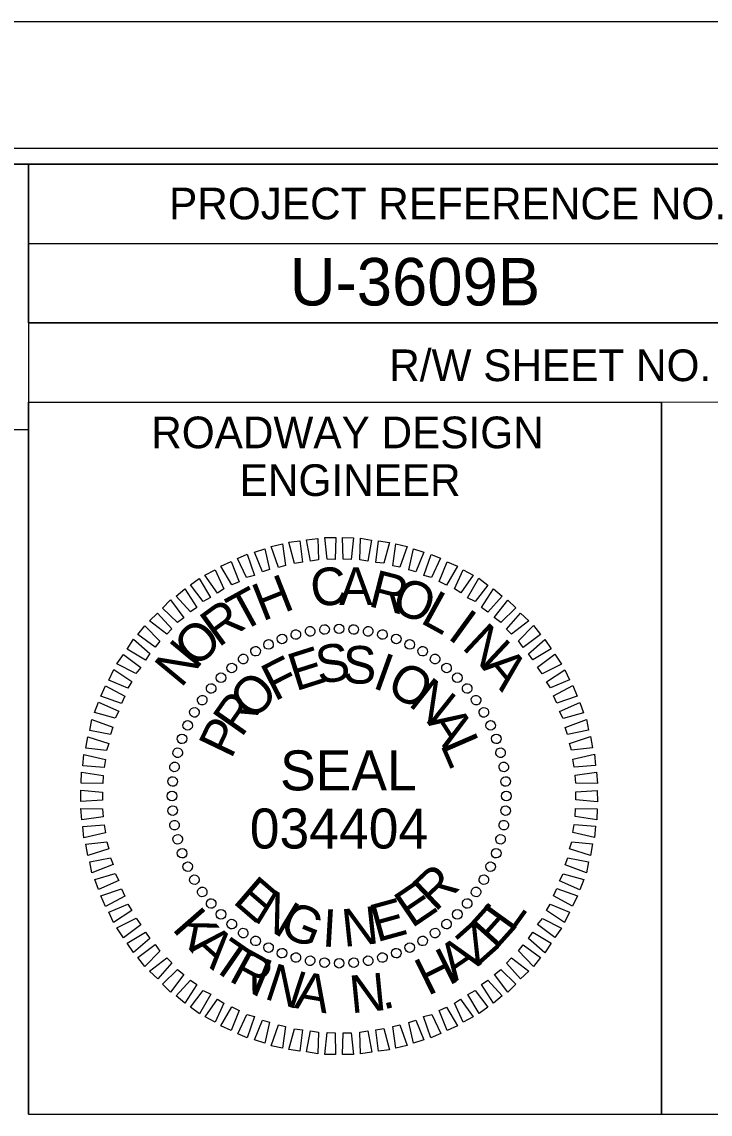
# Model space of a CAD drawing. Extents: x 2568837 to 2570520, y 536545 to 537640.
# Drawn here: x 2570302.1 to 2570410.9, y 537467.1 to 537639.6 of the extents above; entities that cross this region are included whole.
import ezdxf

# ---------------------------------------------------------------- set-up
doc = ezdxf.new("R2010")
doc.units = 0
for name, color, linetype in [('Scratch_Level_0', 7, 'Continuous'), ('Sheet Cutting Line CELL', 7, 'Continuous'), ('Sheet Data Field CELL', 7, 'Continuous'), ('Sheet Plan CELL', 7, 'Continuous'), ('Sheet Plan Layout CELL', 7, 'Continuous'), ('Sheet Plot Border Inside CELL', 7, 'Continuous'), ('Sheet Plot Border Outside CELL', 7, 'Continuous')]:
    doc.layers.add(name, color=color, linetype=linetype)

msp = doc.modelspace()

# ---------------------------------------------------------------- linework, layer by layer
at = {"layer": 'Scratch_Level_0'}
msp.add_lwpolyline([(2570183.85, 537617.15), (2570303.14, 537617.16), (2570303.15, 537575.21), (2570183.85, 537575.19)], close=True, dxfattribs=at)
at = {"layer": 'Sheet Cutting Line CELL'}
msp.add_line((2570520.19, 537639.64), (2568836.69, 537639.64), dxfattribs=at)
at = {"layer": 'Sheet Data Field CELL'}
for p, q in [((2570347.66, 537543.35), (2570347.66, 537543.35)), ((2570349.92, 537543.71), (2570349.92, 537543.71)), ((2570352.24, 537543.8), (2570352.24, 537543.8)), ((2570354.56, 537543.68), (2570354.56, 537543.68)), ((2570356.83, 537543.35), (2570356.83, 537543.35)), ((2570341.06, 537541.34), (2570341.06, 537541.34)), ((2570343.15, 537542.22), (2570343.15, 537542.22)), ((2570345.35, 537542.89), (2570345.35, 537542.89)), ((2570359.05, 537542.92), (2570359.05, 537542.92)), ((2570361.27, 537542.22), (2570361.27, 537542.22)), ((2570339.03, 537540.25), (2570339.03, 537540.25)), ((2570363.39, 537541.31), (2570363.39, 537541.31)), ((2570365.47, 537540.29), (2570365.47, 537540.29)), ((2570337.05, 537539), (2570337.05, 537539)), ((2570367.38, 537539.01), (2570367.38, 537539.01)), ((2570335.23, 537537.66), (2570335.23, 537537.66)), ((2570369.25, 537537.62), (2570369.25, 537537.62)), ((2570333.52, 537536.05), (2570333.52, 537536.05)), ((2570370.91, 537536.07), (2570370.91, 537536.07)), ((2570331.97, 537534.39), (2570331.97, 537534.39)), ((2570372.52, 537534.36), (2570372.52, 537534.36)), ((2570330.58, 537532.52), (2570330.58, 537532.52)), ((2570373.87, 537532.54), (2570373.87, 537532.54)), ((2570329.29, 537530.6), (2570329.29, 537530.6)), ((2570375.12, 537530.56), (2570375.12, 537530.56)), ((2570328.28, 537528.53), (2570328.28, 537528.53)), ((2570376.2, 537528.52), (2570376.2, 537528.52)), ((2570327.37, 537526.41), (2570327.37, 537526.41)), ((2570377.08, 537526.43), (2570377.08, 537526.43)), ((2570326.67, 537524.18), (2570326.67, 537524.18)), ((2570377.75, 537524.23), (2570377.75, 537524.23)), ((2570326.23, 537521.96), (2570326.23, 537521.96)), ((2570378.22, 537521.92), (2570378.22, 537521.92)), ((2570325.9, 537519.69), (2570325.9, 537519.69)), ((2570378.57, 537519.66), (2570378.57, 537519.66)), ((2570325.79, 537517.37), (2570325.79, 537517.37)), ((2570378.66, 537517.35), (2570378.66, 537517.35)), ((2570325.88, 537515.06), (2570325.88, 537515.06)), ((2570378.55, 537515.03), (2570378.55, 537515.03)), ((2570326.23, 537512.8), (2570326.23, 537512.8)), ((2570378.22, 537512.76), (2570378.22, 537512.76)), ((2570326.7, 537510.49), (2570326.7, 537510.49)), ((2570377.78, 537510.54), (2570377.78, 537510.54)), ((2570327.37, 537508.29), (2570327.37, 537508.29)), ((2570377.08, 537508.31), (2570377.08, 537508.31)), ((2570328.25, 537506.2), (2570328.25, 537506.2)), ((2570376.17, 537506.19), (2570376.17, 537506.19)), ((2570329.33, 537504.16), (2570329.33, 537504.16)), ((2570375.16, 537504.12), (2570375.16, 537504.12)), ((2570330.58, 537502.18), (2570330.58, 537502.18)), ((2570373.87, 537502.2), (2570373.87, 537502.2)), ((2570331.93, 537500.36), (2570331.93, 537500.36)), ((2570372.48, 537500.33), (2570372.48, 537500.33)), ((2570333.54, 537498.65), (2570333.54, 537498.65)), ((2570370.93, 537498.67), (2570370.93, 537498.67)), ((2570335.2, 537497.1), (2570335.2, 537497.1)), ((2570369.22, 537497.06), (2570369.22, 537497.06)), ((2570337.07, 537495.71), (2570337.07, 537495.71)), ((2570367.4, 537495.72), (2570367.4, 537495.72)), ((2570338.98, 537494.43), (2570338.98, 537494.43)), ((2570341.06, 537493.41), (2570341.06, 537493.41)), ((2570363.39, 537493.38), (2570363.39, 537493.38)), ((2570365.42, 537494.47), (2570365.42, 537494.47)), ((2570343.18, 537492.5), (2570343.18, 537492.5)), ((2570345.4, 537491.8), (2570345.4, 537491.8)), ((2570347.62, 537491.37), (2570347.62, 537491.37)), ((2570356.79, 537491.37), (2570356.79, 537491.37)), ((2570359.1, 537491.83), (2570359.1, 537491.83)), ((2570361.3, 537492.5), (2570361.3, 537492.5)), ((2570349.89, 537491.04), (2570349.89, 537491.04)), ((2570352.21, 537490.92), (2570352.21, 537490.92)), ((2570354.53, 537491.01), (2570354.53, 537491.01))]:
    msp.add_line(p, q, dxfattribs=at)
for points in [[(2570342.64, 537553.48), (2570341.48, 537556.78), (2570343.26, 537557.18), (2570343.74, 537553.76)], [(2570345.16, 537554.1), (2570344.26, 537557.46), (2570345.99, 537557.65), (2570346.42, 537554.28)], [(2570347.68, 537554.46), (2570347.04, 537557.82), (2570348.83, 537558.06), (2570348.94, 537554.64)], [(2570350.31, 537554.77), (2570349.98, 537558.19), (2570351.72, 537558.17), (2570351.57, 537554.74)], [(2570352.84, 537554.76), (2570352.78, 537558.19), (2570354.51, 537558.16), (2570354.1, 537554.73)], [(2570355.47, 537554.65), (2570355.62, 537558.08), (2570357.36, 537557.79), (2570356.74, 537554.46)], [(2570358.01, 537554.27), (2570358.42, 537557.65), (2570360.16, 537557.42), (2570359.27, 537554.14)], [(2570360.7, 537553.74), (2570361.17, 537557.17), (2570362.97, 537556.78), (2570361.81, 537553.5)], [(2570337.56, 537551.86), (2570336.14, 537554.89), (2570337.71, 537555.55), (2570338.87, 537552.2)], [(2570340.13, 537552.75), (2570338.86, 537555.89), (2570340.48, 537556.39), (2570341.22, 537553.14)], [(2570363.24, 537553.1), (2570363.97, 537556.38), (2570365.61, 537555.88), (2570364.35, 537552.75)], [(2570365.63, 537552.2), (2570366.78, 537555.53), (2570368.26, 537554.93), (2570366.84, 537551.85)], [(2570335.26, 537550.72), (2570333.53, 537553.64), (2570335.15, 537554.4), (2570336.41, 537551.21)], [(2570368.01, 537551.24), (2570369.28, 537554.37), (2570370.92, 537553.66), (2570369.18, 537550.68)], [(2570330.73, 537548.06), (2570328.73, 537550.71), (2570330.08, 537551.73), (2570331.87, 537548.71)], [(2570333.02, 537549.41), (2570331.02, 537552.22), (2570332.64, 537553.09), (2570334.01, 537550.06)], [(2570370.46, 537550.07), (2570371.82, 537553.09), (2570373.42, 537552.23), (2570371.47, 537549.45)], [(2570372.53, 537548.68), (2570374.32, 537551.77), (2570375.71, 537550.69), (2570373.7, 537548.07)], [(2570328.75, 537546.44), (2570326.45, 537548.93), (2570327.85, 537550.06), (2570329.74, 537547.15)], [(2570374.72, 537547.14), (2570376.62, 537550.07), (2570378.01, 537548.94), (2570375.73, 537546.42)], [(2570326.68, 537544.77), (2570324.32, 537547.05), (2570325.56, 537548.34), (2570327.66, 537545.53)], [(2570376.75, 537545.54), (2570378.86, 537548.32), (2570380.15, 537547.08), (2570377.76, 537544.77)], [(2570324.97, 537542.9), (2570322.25, 537545.01), (2570323.54, 537546.25), (2570325.8, 537543.76)], [(2570378.68, 537543.73), (2570380.9, 537546.25), (2570382.18, 537545.01), (2570379.48, 537542.9)], [(2570323.16, 537540.87), (2570320.39, 537542.87), (2570321.52, 537544.26), (2570323.88, 537541.83)], [(2570380.55, 537541.87), (2570382.93, 537544.28), (2570384.06, 537542.88), (2570381.31, 537540.83)], [(2570321.62, 537538.84), (2570318.74, 537540.58), (2570319.72, 537542.12), (2570322.29, 537539.85)], [(2570382.17, 537539.84), (2570384.71, 537542.1), (2570385.74, 537540.59), (2570382.82, 537538.86)], [(2570320.08, 537536.71), (2570317.1, 537538.23), (2570318.13, 537539.73), (2570320.9, 537537.67)], [(2570383.58, 537537.71), (2570386.33, 537539.76), (2570387.36, 537538.2), (2570384.33, 537536.67)], [(2570318.85, 537534.42), (2570315.83, 537535.68), (2570316.59, 537537.33), (2570319.47, 537535.43)], [(2570384.98, 537535.42), (2570387.9, 537537.31), (2570388.61, 537535.69), (2570385.63, 537534.43)], [(2570317.84, 537531.98), (2570314.56, 537533.13), (2570315.32, 537534.78), (2570318.35, 537533.15)], [(2570386.08, 537533.17), (2570389.16, 537534.81), (2570389.87, 537533.13), (2570386.62, 537532.02)], [(2570316.83, 537529.64), (2570313.55, 537530.54), (2570314.2, 537532.18), (2570317.39, 537530.76)], [(2570387.07, 537530.71), (2570390.26, 537532.14), (2570390.86, 537530.52), (2570387.61, 537529.62)], [(2570316.08, 537527.1), (2570312.81, 537527.73), (2570313.14, 537529.47), (2570316.48, 537528.22)], [(2570387.95, 537528.2), (2570391.3, 537529.47), (2570391.65, 537527.74), (2570388.34, 537527.1)], [(2570315.44, 537524.56), (2570312.17, 537524.93), (2570312.51, 537526.73), (2570315.84, 537525.68)], [(2570388.63, 537525.68), (2570391.93, 537526.74), (2570392.28, 537524.96), (2570388.97, 537524.58)], [(2570315.07, 537521.87), (2570311.69, 537522.13), (2570311.87, 537523.92), (2570315.31, 537523.14)], [(2570389.15, 537523.17), (2570392.56, 537523.96), (2570392.75, 537522.18), (2570389.38, 537521.91)], [(2570314.85, 537519.34), (2570311.43, 537519.39), (2570311.5, 537521.12), (2570314.93, 537520.61)], [(2570389.51, 537520.64), (2570392.92, 537521.13), (2570393.06, 537519.34), (2570389.64, 537519.38)], [(2570314.84, 537516.71), (2570311.42, 537516.49), (2570311.39, 537518.28), (2570314.82, 537517.97)], [(2570389.61, 537518.01), (2570393.03, 537518.23), (2570393.06, 537516.44), (2570389.63, 537516.75)], [(2570314.94, 537514.07), (2570311.53, 537513.59), (2570311.39, 537515.38), (2570314.81, 537515.34)], [(2570389.6, 537515.38), (2570393.02, 537515.33), (2570392.95, 537513.59), (2570389.52, 537514.11)], [(2570315.3, 537511.55), (2570311.89, 537510.76), (2570311.7, 537512.54), (2570315.07, 537512.81)], [(2570389.38, 537512.85), (2570392.76, 537512.59), (2570392.58, 537510.8), (2570389.14, 537511.58)], [(2570315.82, 537509.03), (2570312.52, 537507.98), (2570312.17, 537509.76), (2570315.48, 537510.13)], [(2570389.01, 537510.15), (2570392.28, 537509.79), (2570391.94, 537507.99), (2570388.61, 537509.04)], [(2570316.5, 537506.52), (2570313.15, 537505.25), (2570312.8, 537506.98), (2570316.11, 537507.62)], [(2570388.37, 537507.62), (2570391.64, 537506.99), (2570391.3, 537505.24), (2570387.96, 537506.5)], [(2570317.38, 537504.01), (2570314.19, 537502.58), (2570313.59, 537504.2), (2570316.84, 537505.1)], [(2570387.62, 537505.07), (2570390.9, 537504.18), (2570390.25, 537502.54), (2570387.06, 537503.96)], [(2570318.37, 537501.55), (2570315.29, 537499.91), (2570314.58, 537501.59), (2570317.83, 537502.7)], [(2570386.61, 537502.74), (2570389.89, 537501.59), (2570389.13, 537499.94), (2570386.1, 537501.57)], [(2570319.47, 537499.3), (2570316.55, 537497.41), (2570315.84, 537499.03), (2570318.82, 537500.29)], [(2570385.6, 537500.3), (2570388.62, 537499.03), (2570387.86, 537497.39), (2570384.98, 537499.29)], [(2570320.87, 537497.01), (2570318.12, 537494.96), (2570317.09, 537496.52), (2570320.12, 537498.05)], [(2570384.37, 537498.01), (2570387.35, 537496.48), (2570386.32, 537494.99), (2570383.55, 537497.05)], [(2570322.28, 537494.87), (2570319.74, 537492.62), (2570318.71, 537494.13), (2570321.63, 537495.86)], [(2570382.83, 537495.88), (2570385.71, 537494.14), (2570384.73, 537492.59), (2570382.16, 537494.87)], [(2570323.9, 537492.85), (2570321.52, 537490.44), (2570320.39, 537491.84), (2570323.14, 537493.89)], [(2570381.29, 537493.85), (2570384.06, 537491.85), (2570382.93, 537490.46), (2570380.57, 537492.89)], [(2570325.77, 537490.99), (2570323.55, 537488.47), (2570322.27, 537489.71), (2570324.97, 537491.81)], [(2570379.48, 537491.82), (2570382.2, 537489.71), (2570380.91, 537488.47), (2570378.65, 537490.96)], [(2570327.7, 537489.18), (2570325.59, 537486.4), (2570324.3, 537487.64), (2570326.69, 537489.95)], [(2570377.77, 537489.94), (2570380.13, 537487.67), (2570378.89, 537486.38), (2570376.79, 537489.19)], [(2570329.73, 537487.58), (2570327.83, 537484.65), (2570326.44, 537485.78), (2570328.72, 537488.3)], [(2570375.7, 537488.28), (2570378, 537485.79), (2570376.6, 537484.66), (2570374.71, 537487.57)], [(2570331.92, 537486.04), (2570330.13, 537482.95), (2570328.74, 537484.03), (2570330.75, 537486.65)], [(2570373.72, 537486.66), (2570375.72, 537484.01), (2570374.37, 537482.99), (2570372.58, 537486.01)], [(2570333.99, 537484.65), (2570332.63, 537481.62), (2570331.03, 537482.49), (2570332.98, 537485.27)], [(2570371.43, 537485.3), (2570373.43, 537482.5), (2570371.81, 537481.62), (2570370.44, 537484.66)], [(2570336.44, 537483.48), (2570335.18, 537480.35), (2570333.53, 537481.06), (2570335.27, 537484.04)], [(2570338.82, 537482.52), (2570337.67, 537479.19), (2570336.19, 537479.79), (2570337.61, 537482.87)], [(2570366.89, 537482.86), (2570368.31, 537479.83), (2570366.74, 537479.17), (2570365.58, 537482.52)], [(2570369.19, 537484), (2570370.92, 537481.08), (2570369.3, 537480.32), (2570368.04, 537483.51)], [(2570341.21, 537481.62), (2570340.48, 537478.34), (2570338.84, 537478.84), (2570340.1, 537481.97)], [(2570343.75, 537480.98), (2570343.28, 537477.55), (2570341.49, 537477.93), (2570342.64, 537481.22)], [(2570361.81, 537481.24), (2570362.97, 537477.94), (2570361.19, 537477.54), (2570360.71, 537480.96)], [(2570364.32, 537481.97), (2570365.59, 537478.83), (2570363.97, 537478.33), (2570363.23, 537481.58)], [(2570346.44, 537480.44), (2570346.03, 537477.07), (2570344.29, 537477.3), (2570345.18, 537480.58)], [(2570348.98, 537480.07), (2570348.83, 537476.64), (2570347.08, 537476.93), (2570347.71, 537480.26)], [(2570351.61, 537479.95), (2570351.67, 537476.53), (2570349.94, 537476.55), (2570350.35, 537479.99)], [(2570354.14, 537479.95), (2570354.47, 537476.53), (2570352.73, 537476.55), (2570352.88, 537479.98)], [(2570356.77, 537480.26), (2570357.41, 537476.9), (2570355.62, 537476.65), (2570355.51, 537480.08)], [(2570359.29, 537480.62), (2570360.19, 537477.26), (2570358.46, 537477.07), (2570358.03, 537480.44)]]:
    msp.add_lwpolyline(points, close=True, dxfattribs=at)
for centre, major_axis in [((2570345.39, 537542.87), (-0.196, 0.732)), ((2570347.64, 537543.37), (-0.132, 0.747)), ((2570349.92, 537543.67), (-0.066, 0.755)), ((2570352.22, 537543.77), (0, 0.758)), ((2570354.53, 537543.67), (0.066, 0.755)), ((2570356.81, 537543.37), (0.132, 0.747)), ((2570359.06, 537542.87), (0.196, 0.732)), ((2570341.06, 537541.3), (-0.32, 0.687)), ((2570343.19, 537542.18), (-0.259, 0.713)), ((2570361.26, 537542.18), (0.259, 0.713)), ((2570363.39, 537541.3), (0.32, 0.687)), ((2570337.07, 537539), (-0.435, 0.621)), ((2570339.02, 537540.23), (-0.379, 0.657)), ((2570365.43, 537540.23), (0.379, 0.657)), ((2570367.38, 537539), (0.435, 0.621)), ((2570335.25, 537537.59), (-0.487, 0.581)), ((2570369.2, 537537.59), (0.487, 0.581)), ((2570333.55, 537536.04), (-0.536, 0.536)), ((2570370.9, 537536.04), (0.536, 0.536)), ((2570331.99, 537534.34), (-0.581, 0.487)), ((2570372.46, 537534.34), (0.581, 0.487)), ((2570330.59, 537532.51), (-0.621, 0.435)), ((2570373.86, 537532.51), (0.621, 0.435)), ((2570329.35, 537530.57), (-0.657, 0.379)), ((2570375.1, 537530.57), (0.657, 0.379)), ((2570328.29, 537528.52), (-0.687, 0.32)), ((2570376.16, 537528.52), (0.687, 0.32)), ((2570327.4, 537526.39), (-0.713, 0.259)), ((2570377.05, 537526.39), (0.713, 0.259)), ((2570326.71, 537524.2), (-0.732, 0.196)), ((2570377.74, 537524.2), (0.732, 0.196)), ((2570326.21, 537521.95), (-0.747, 0.132)), ((2570378.24, 537521.95), (0.747, 0.132)), ((2570325.91, 537519.66), (-0.755, 0.066)), ((2570378.54, 537519.66), (0.755, 0.066)), ((2570325.81, 537517.36), (-0.758, 0)), ((2570378.64, 537517.36), (0.758, 0)), ((2570325.91, 537515.06), (-0.755, -0.066)), ((2570378.54, 537515.06), (0.755, -0.066)), ((2570326.21, 537512.77), (-0.747, -0.132)), ((2570378.24, 537512.77), (0.747, -0.132)), ((2570326.71, 537510.52), (-0.732, -0.196)), ((2570377.74, 537510.52), (0.732, -0.196)), ((2570327.4, 537508.33), (-0.713, -0.259)), ((2570377.05, 537508.33), (0.713, -0.259)), ((2570328.29, 537506.2), (-0.687, -0.32)), ((2570376.16, 537506.2), (0.687, -0.32)), ((2570329.35, 537504.15), (-0.657, -0.379)), ((2570375.1, 537504.15), (0.657, -0.379)), ((2570330.59, 537502.21), (-0.621, -0.435)), ((2570373.86, 537502.21), (0.621, -0.435)), ((2570331.99, 537500.38), (-0.581, -0.487)), ((2570372.46, 537500.38), (0.581, -0.487)), ((2570333.55, 537498.68), (-0.536, -0.536)), ((2570370.9, 537498.68), (0.536, -0.536)), ((2570335.25, 537497.13), (-0.487, -0.581)), ((2570337.07, 537495.72), (-0.435, -0.621)), ((2570367.38, 537495.72), (0.435, -0.621)), ((2570369.2, 537497.13), (0.487, -0.581)), ((2570339.02, 537494.48), (-0.379, -0.657)), ((2570365.43, 537494.48), (0.379, -0.657)), ((2570341.06, 537493.42), (-0.32, -0.687)), ((2570343.19, 537492.54), (-0.259, -0.713)), ((2570361.26, 537492.54), (0.259, -0.713)), ((2570363.39, 537493.42), (0.32, -0.687)), ((2570345.39, 537491.85), (-0.196, -0.732)), ((2570347.64, 537491.35), (-0.132, -0.747)), ((2570349.92, 537491.05), (-0.066, -0.755)), ((2570352.23, 537490.95), (0, -0.758)), ((2570354.53, 537491.05), (0.066, -0.755)), ((2570356.81, 537491.35), (0.132, -0.747)), ((2570359.06, 537491.85), (0.196, -0.732))]:
    msp.add_ellipse(centre, major_axis=major_axis, ratio=0.999708, dxfattribs=at)
at = {"layer": 'Sheet Plan CELL'}
for p, q in [((2570303.13, 537604.61), (2570503.18, 537604.6)), ((2570303.14, 537592.08), (2570503.18, 537592.1)), ((2570303.14, 537592.08), (2570503.18, 537592.1)), ((2570303.14, 537592.08), (2570303.14, 537579.59)), ((2570403.19, 537579.59), (2570403.2, 537467.13))]:
    msp.add_line(p, q, dxfattribs=at)
for points in [[(2569003.18, 536567.15), (2569003.15, 537617.13), (2570303.14, 537617.16), (2570303.15, 537467.1), (2570503.19, 537467.09), (2570503.19, 536567.15)], [(2570503.22, 537617.15), (2569003.18, 537617.15), (2569003.18, 536567.15), (2570503.19, 536567.15)], [(2570303.14, 537617.16), (2570503.22, 537617.15), (2570503.18, 537592.1), (2570303.14, 537592.08)], [(2570303.14, 537579.59), (2570403.19, 537579.59), (2570403.19, 537467.08), (2570303.15, 537467.1)], [(2570403.19, 537579.59), (2570503.18, 537579.6), (2570503.19, 537467.09), (2570403.19, 537467.08)]]:
    msp.add_lwpolyline(points, close=True, dxfattribs=at)
at = {"layer": 'Sheet Plan Layout CELL'}
msp.add_lwpolyline([(2570263.93, 537405.66), (2570503.2, 537405.66), (2570503.23, 537617.15), (2570263.93, 537617.15)], close=True, dxfattribs=at)
at = {"layer": 'Sheet Plot Border Inside CELL'}
msp.add_lwpolyline([(2568849.69, 536564.64), (2570515.68, 536564.65), (2570515.69, 537619.64), (2568849.69, 537619.64)], close=True, dxfattribs=at)
at = {"layer": 'Sheet Plot Border Outside CELL'}
msp.add_lwpolyline([(2568836.69, 536544.64), (2570520.19, 536544.64), (2570520.19, 537639.64), (2568836.69, 537639.64)], close=True, dxfattribs=at)

# ---------------------------------------------------------------- texts
at = {"layer": 'Sheet Data Field CELL'}
for s, height, rotation, p in [('U-3609B', 7.5, 0, (2570344.42, 537594.84)), ('C', 5.94, 7.2205, (2570348.07, 537547.15)), ('A', 5.94, 0.021, (2570352.22, 537547.54)), ('H', 5.94, 21.6201, (2570340.1, 537544.9)), ('R', 5.94, 345.6217, (2570356.65, 537547.4)), ('T', 5.94, 28.8204, (2570336.71, 537543.11)), ('O', 5.94, 338.4218, (2570360.19, 537546.68)), ('L', 5.94, 331.2215, (2570364.86, 537544.81)), ('R', 5.94, 36.0212, (2570333.17, 537540.73)), ('I', 5.94, 324.0208, (2570369.17, 537542.36)), ('O', 5.94, 43.2224, (2570329.6, 537537.4)), ('N', 5.94, 316.8196, (2570371.46, 537540.76)), ('N', 5.94, 50.4241, (2570327.23, 537534.3)), ('S', 5.94, 8.2563, (2570348.97, 537535.05)), ('E', 5.94, 17.6117, (2570345.35, 537533.88)), ('S', 5.94, 358.901, (2570352.76, 537535.17)), ('I', 5.94, 340.1903, (2570357.3, 537534.51)), ('A', 5.94, 309.6178, (2570374.62, 537537.71)), ('F', 5.94, 26.9677, (2570342.01, 537532.24)), ('O', 5.94, 330.8341, (2570359.42, 537533.81)), ('O', 5.94, 45.6819, (2570338.59, 537529.08)), ('N', 5.94, 321.4773, (2570362.98, 537531.77)), ('R', 5.94, 55.0403, (2570336.79, 537526.46)), ('P', 5.94, 64.3995, (2570335.17, 537523.07)), ('A', 5.94, 302.7609, (2570366.03, 537529.08)), ('L', 5.94, 293.4015, (2570368.15, 537525.49)), ('SEAL', 6.317, 0.0006, (2570342.89, 537518.25)), ('034404', 6.319, 0.0006, (2570338.1, 537509.07)), ('R', 5.94, 43.4821, (2570367.4, 537498.93)), ('E', 5.94, 319.2775, (2570335.24, 537500.58)), ('E', 5.94, 34.1247, (2570363.7, 537496.39)), ('N', 5.94, 328.6346, (2570338.45, 537497.79)), ('G', 5.94, 337.9909, (2570342.49, 537495.49)), ('N', 5.94, 6.057, (2570352.96, 537493.51)), ('E', 5.94, 15.4124, (2570358.16, 537494.24)), ('E', 5.94, 48.1249, (2570377, 537492.93)), ('L', 5.94, 54.2997, (2570379.49, 537495.67)), ('K', 5.94, 311.1686, (2570325.68, 537496.34)), ('I', 5.94, 356.7018, (2570349.43, 537493.61)), ('Z', 5.94, 41.5854, (2570374.06, 537490.34)), ('A', 5.94, 318.0728, (2570328.41, 537493.23)), ('T', 5.94, 325.3226, (2570331.65, 537490.33)), ('R', 5.94, 331.3054, (2570334.58, 537488.27)), ('H', 5.94, 26.3758, (2570366.23, 537485.72)), ('A', 5.94, 34.3357, (2570370.48, 537487.88)), ('I', 5.94, 337.7105, (2570337.94, 537486.41)), ('N', 5.94, 341.8314, (2570340.2, 537485.42)), ('A', 5.94, 350.252, (2570345.01, 537483.91)), ('N', 5.94, 5.596, (2570354.14, 537483.03)), ('.', 5.94, 14.0166, (2570359.15, 537483.59))]:
    msp.add_text(s, height=height, rotation=rotation, dxfattribs=at).set_placement(p)
at = {"layer": 'Sheet Plan CELL'}
for s, height, p in [('PROJECT REFERENCE NO.', 5.0001, (2570325.34, 537608.44)), ('R/W SHEET NO.', 5.0001, (2570360.14, 537582.89)), ('ROADWAY DESIGN', 5.0001, (2570322.52, 537572.29)), ('ROADWAY DESIGN', 5.0001, (2570322.52, 537572.29)), ('ENGINEER', 5, (2570336.5, 537564.75))]:
    msp.add_text(s, height=height, rotation=0, dxfattribs=at).set_placement(p)

doc.saveas('drawing.dxf')
